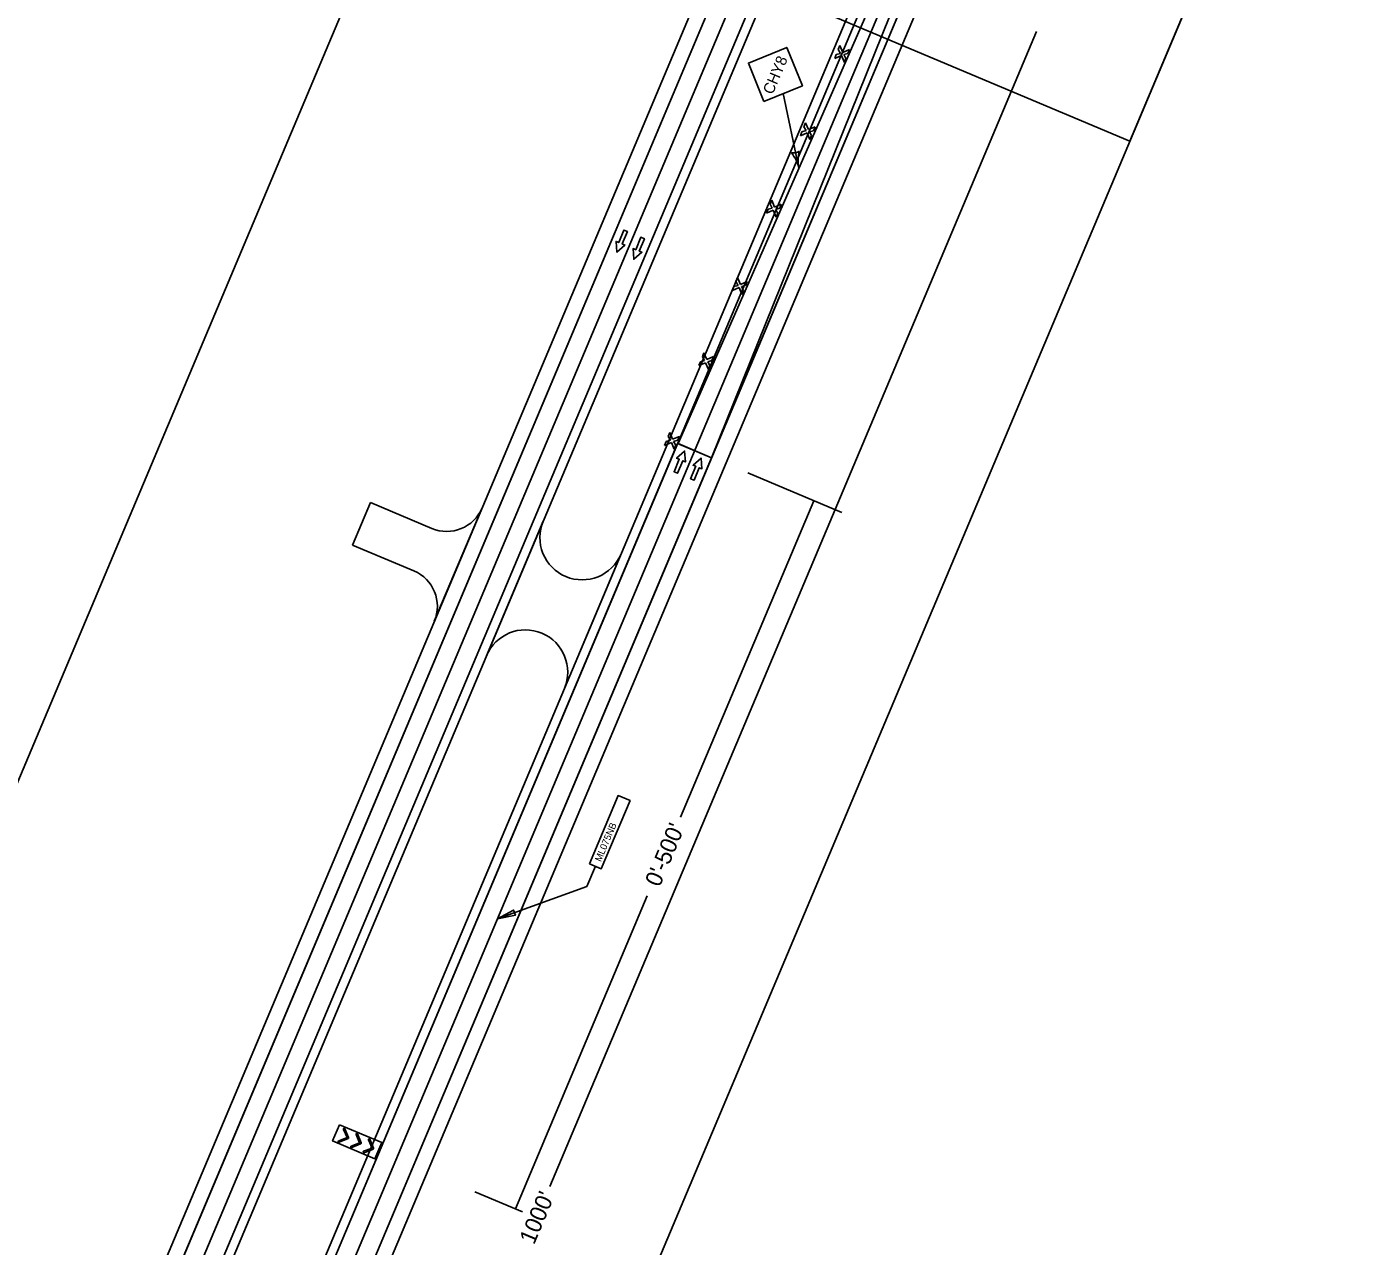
# Model space of a CAD drawing. Extents: x 14104283 to 14128447, y 8633203 to 8671666.
# Drawn here: x 14117804 to 14118675, y 8666247 to 8667040 of the extents above; entities that cross this region are included whole.
import ezdxf

# ---------------------------------------------------------------- set-up
doc = ezdxf.new("R2010")
doc.units = 0
for name, color, linetype in [('Cell', 7, 'Continuous'), ('Default', 7, 'Continuous'), ('dsnNonPlotable', 7, 'Continuous'), ('dsnPaintExistingBrokenLaneLineWhite', 7, 'Continuous'), ('dsnPaintExistingEdgeLineLeftYellow', 7, 'Continuous'), ('dsnPaintExistingEdgeLineRightWhite', 7, 'Continuous'), ('dsnShadingPaved', 7, 'Continuous'), ('dsnStdLabel', 7, 'Continuous'), ('dsnStgShadingPrevPav', 7, 'Continuous'), ('dsnTapePlaceChannelizingLaneYellow', 7, 'Continuous'), ('dsnTapeRemoveChannelizingWhite', 7, 'Continuous'), ('Text', 7, 'Continuous')]:
    doc.layers.add(name, color=color, linetype=linetype)

msp = doc.modelspace()

# ---------------------------------------------------------------- linework, layer by layer
at = {"layer": 'Cell'}
for p, q in [((14118333.3, 8667028.02), (14118332.27, 8667025.47)), ((14118335.17, 8667023.63), (14118333.3, 8667028.02)), ((14118330.96, 8667022.22), (14118329.94, 8667019.67)), ((14118329.94, 8667019.67), (14118334.33, 8667021.54)), ((14118333.7, 8667023), (14118330.96, 8667022.22)), ((14118332.27, 8667025.47), (14118333.7, 8667023)), ((14118334.33, 8667021.54), (14118336.2, 8667017.15)), ((14118339.56, 8667025.5), (14118335.17, 8667023.63)), ((14118335.79, 8667022.16), (14118338.53, 8667022.95)), ((14118337.22, 8667019.7), (14118335.79, 8667022.16)), ((14118336.2, 8667017.15), (14118337.22, 8667019.7)), ((14118338.53, 8667022.95), (14118339.56, 8667025.5)), ((14118310.93, 8666977.77), (14118309.91, 8666975.22)), ((14118309.91, 8666975.22), (14118311.34, 8666972.75)), ((14118312.8, 8666973.37), (14118310.93, 8666977.77)), ((14118317.2, 8666975.24), (14118312.8, 8666973.37)), ((14118316.17, 8666972.69), (14118317.2, 8666975.24)), ((14118308.6, 8666971.97), (14118307.57, 8666969.42)), ((14118307.57, 8666969.42), (14118311.96, 8666971.29)), ((14118311.34, 8666972.75), (14118308.6, 8666971.97)), ((14118311.96, 8666971.29), (14118313.83, 8666966.9)), ((14118313.43, 8666971.91), (14118316.17, 8666972.69)), ((14118314.86, 8666969.45), (14118313.43, 8666971.91)), ((14118313.83, 8666966.9), (14118314.86, 8666969.45)), ((14118289.33, 8666922.35), (14118286.59, 8666921.57)), ((14118288.92, 8666927.37), (14118287.89, 8666924.81)), ((14118287.89, 8666924.81), (14118289.33, 8666922.35)), ((14118290.79, 8666922.97), (14118288.92, 8666927.37)), ((14118295.18, 8666924.84), (14118290.79, 8666922.97)), ((14118291.41, 8666921.51), (14118294.16, 8666922.29)), ((14118294.16, 8666922.29), (14118295.18, 8666924.84)), ((14118286.59, 8666921.57), (14118285.56, 8666919.02)), ((14118285.56, 8666919.02), (14118289.95, 8666920.89)), ((14118289.95, 8666920.89), (14118291.82, 8666916.5)), ((14118292.85, 8666919.05), (14118291.41, 8666921.51)), ((14118291.82, 8666916.5), (14118292.85, 8666919.05)), ((14118264.35, 8666871.26), (14118263.32, 8666868.71)), ((14118263.32, 8666868.71), (14118267.71, 8666870.58)), ((14118267.09, 8666872.04), (14118264.35, 8666871.26)), ((14118266.69, 8666877.06), (14118265.66, 8666874.51)), ((14118265.66, 8666874.51), (14118267.09, 8666872.04)), ((14118268.56, 8666872.67), (14118266.69, 8666877.06)), ((14118267.71, 8666870.58), (14118269.58, 8666866.19)), ((14118272.95, 8666874.54), (14118268.56, 8666872.67)), ((14118269.18, 8666871.2), (14118271.92, 8666871.99)), ((14118270.61, 8666868.74), (14118269.18, 8666871.2)), ((14118271.92, 8666871.99), (14118272.95, 8666874.54)), ((14118269.58, 8666866.19), (14118270.61, 8666868.74)), ((14118244.83, 8666828.19), (14118243.8, 8666825.64)), ((14118246.7, 8666823.8), (14118244.83, 8666828.19)), ((14118242.49, 8666822.39), (14118241.46, 8666819.84)), ((14118241.46, 8666819.84), (14118245.86, 8666821.71)), ((14118245.23, 8666823.18), (14118242.49, 8666822.39)), ((14118243.8, 8666825.64), (14118245.23, 8666823.18)), ((14118245.86, 8666821.71), (14118247.73, 8666817.32)), ((14118251.09, 8666825.67), (14118246.7, 8666823.8)), ((14118247.32, 8666822.33), (14118250.06, 8666823.12)), ((14118248.75, 8666819.87), (14118247.32, 8666822.33)), ((14118247.73, 8666817.32), (14118248.75, 8666819.87)), ((14118250.06, 8666823.12), (14118251.09, 8666825.67)), ((14118222.59, 8666776.29), (14118221.56, 8666773.74)), ((14118224.46, 8666771.9), (14118222.59, 8666776.29)), ((14118220.25, 8666770.49), (14118219.23, 8666767.94)), ((14118219.23, 8666767.94), (14118223.62, 8666769.81)), ((14118223, 8666771.27), (14118220.25, 8666770.49)), ((14118221.56, 8666773.74), (14118223, 8666771.27)), ((14118223.62, 8666769.81), (14118225.49, 8666765.42)), ((14118228.85, 8666773.77), (14118224.46, 8666771.9)), ((14118225.08, 8666770.43), (14118227.82, 8666771.22)), ((14118226.52, 8666767.97), (14118225.08, 8666770.43)), ((14118225.49, 8666765.42), (14118226.52, 8666767.97)), ((14118227.82, 8666771.22), (14118228.85, 8666773.77)), ((14118013.61, 8666317.52), (14118011.26, 8666323.29)), ((14118021.74, 8666314.1), (14118019.39, 8666319.86)), ((14118029.82, 8666310.69), (14118027.47, 8666316.46))]:
    msp.add_line(p, q, dxfattribs=at)
for points in [[(14118192.67, 8666908.01), (14118194.98, 8666907.06), (14118191.66, 8666898.97), (14118193.4, 8666898.26), (14118188.13, 8666893.66), (14118187.61, 8666900.63), (14118189.35, 8666899.92)], [(14118203.74, 8666903.35), (14118206.05, 8666902.4), (14118202.73, 8666894.31), (14118204.46, 8666893.6), (14118199.2, 8666889), (14118198.68, 8666895.97), (14118200.41, 8666895.26)], [(14118227.71, 8666749.82), (14118225.4, 8666750.77), (14118228.72, 8666758.87), (14118226.99, 8666759.58), (14118232.25, 8666764.17), (14118232.77, 8666757.21), (14118231.03, 8666757.92)], [(14118238.48, 8666745.29), (14118236.17, 8666746.23), (14118239.49, 8666754.33), (14118237.76, 8666755.04), (14118243.02, 8666759.64), (14118243.54, 8666752.67), (14118241.8, 8666753.38)], [(14118007.58, 8666325.88), (14118035.23, 8666314.23), (14118030.78, 8666303.66), (14118003.13, 8666315.31)]]:
    msp.add_lwpolyline(points, close=True, dxfattribs=at)
for points in [[(14118189.35, 8666899.92), (14118187.61, 8666900.63), (14118188.13, 8666893.66), (14118193.4, 8666898.26), (14118191.66, 8666898.97), (14118194.98, 8666907.06), (14118192.67, 8666908.01), (14118189.35, 8666899.92)], [(14118200.41, 8666895.26), (14118198.68, 8666895.97), (14118199.2, 8666889), (14118204.46, 8666893.6), (14118202.73, 8666894.31), (14118206.05, 8666902.4), (14118203.74, 8666903.35), (14118200.41, 8666895.26)], [(14118231.03, 8666757.92), (14118232.77, 8666757.21), (14118232.25, 8666764.17), (14118226.99, 8666759.58), (14118228.72, 8666758.87), (14118225.4, 8666750.77), (14118227.71, 8666749.82), (14118231.03, 8666757.92)], [(14118241.8, 8666753.38), (14118243.54, 8666752.67), (14118243.02, 8666759.64), (14118237.76, 8666755.04), (14118239.49, 8666754.33), (14118236.17, 8666746.23), (14118238.48, 8666745.29), (14118241.8, 8666753.38)], [(14118010.3, 8666322.91), (14118010.31, 8666322.88), (14118012.66, 8666317.52), (14118007.18, 8666315.45)], [(14118007.54, 8666314.49), (14118007.56, 8666314.49), (14118013.32, 8666316.84), (14118013.33, 8666316.84)], [(14118018.43, 8666319.48), (14118018.45, 8666319.45), (14118020.79, 8666314.09), (14118015.31, 8666312.03)], [(14118015.67, 8666311.06), (14118015.69, 8666311.07), (14118021.45, 8666313.42), (14118021.46, 8666313.42)], [(14118026.52, 8666316.07), (14118026.53, 8666316.05), (14118028.87, 8666310.69), (14118023.39, 8666308.62)], [(14118023.75, 8666307.66), (14118023.77, 8666307.66), (14118029.54, 8666310.01), (14118029.54, 8666310.01)]]:
    msp.add_lwpolyline(points, dxfattribs=at)
for centre, start, end in [((14118010.78, 8666323.1), 21.87368, 202.05724), ((14118007.35, 8666314.97), 109.79452, 290.9537), ((14118013.13, 8666317.32), 292.54487, 22.99314), ((14118018.91, 8666319.67), 21.87368, 202.05724), ((14118021.26, 8666313.89), 292.54487, 22.99314), ((14118026.99, 8666316.27), 21.87368, 202.05724), ((14118015.49, 8666311.54), 109.79452, 290.9537), ((14118023.57, 8666308.14), 109.79452, 290.9537), ((14118029.35, 8666310.49), 292.54487, 22.99314)]:
    msp.add_arc(centre, 0.515, start, end, dxfattribs=at)
at = {"layer": 'Default'}
for points in [[(14118413.25, 8667444.25), (14110818.39, 8649409.15), (14109142.61, 8645431.44)], [(14109164.73, 8645422.12), (14110840.51, 8649399.84), (14118435.37, 8667434.94)]]:
    msp.add_lwpolyline(points, dxfattribs=at)
at = {"layer": 'dsnNonPlotable'}
for points in [[(14118056.48, 8667161.91), (14118665.06, 8668606.45), (14119130.44, 8668410.38), (14118521.87, 8666965.84)], [(14117486.73, 8665809.52), (14118095.31, 8667254.06), (14118560.69, 8667058), (14117952.12, 8665613.46)]]:
    msp.add_lwpolyline(points, close=True, dxfattribs=at)
at = {"layer": 'dsnPaintExistingBrokenLaneLineWhite'}
for p, q in [((14114932.53, 8658913.38), (14118537.63, 8667474.22)), ((14110829.45, 8649404.5), (14118424.31, 8667439.59))]:
    msp.add_line(p, q, dxfattribs=at)
at = {"layer": 'dsnPaintExistingEdgeLineLeftYellow'}
for p, q in [((14115900.95, 8661243.95), (14118759.37, 8668031.7)), ((14118435.37, 8667434.94), (14115816.14, 8661215.2))]:
    msp.add_line(p, q, dxfattribs=at)
at = {"layer": 'dsnPaintExistingEdgeLineRightWhite'}
for p, q in [((14110924.38, 8649364.51), (14118874.68, 8668243.67)), ((14118413.25, 8667444.25), (14115798.75, 8661235.75))]:
    msp.add_line(p, q, dxfattribs=at)
at = {"layer": 'dsnShadingPaved'}
for p, q in [((14118249.84, 8666759.92), (14118874.67, 8668243.66)), ((14118537.63, 8667474.22), (14118227.96, 8666769.13)), ((14115901.18, 8661244.5), (14118227.72, 8666769.23)), ((14118227.72, 8666769.23), (14118249.84, 8666759.92)), ((14118227.96, 8666769.13), (14118249.84, 8666759.92)), ((14118249.84, 8666759.92), (14115923.29, 8661235.18))]:
    msp.add_line(p, q, dxfattribs=at)
at = {"layer": 'dsnStdLabel'}
for p, q in [((14118461.19, 8667037.24), (14118330.11, 8666726.11)), ((14118296.4, 8666996.79), (14118306.61, 8666948.21)), ((14118334.65, 8666724.2), (14118273.35, 8666750.02)), ((14118316.29, 8666731.94), (14118229.56, 8666526.07)), ((14118330.11, 8666726.11), (14118144.58, 8666285.72)), ((14118207.93, 8666474.74), (14118122.17, 8666271.16)), ((14118126.78, 8666269.22), (14118095.84, 8666282.24))]:
    msp.add_line(p, q, dxfattribs=at)
msp.add_lwpolyline([(14118283.9, 8666991.7), (14118308.9, 8667001.88), (14118298.72, 8667026.88), (14118273.72, 8667016.7)], close=True, dxfattribs=at)
for centre, radius, start, end in [((14118302.65, 8666967.04), 8.86, 264.12916, 299.59761), ((14118284.15, 8666943.49), 22.95, 11.86334, 39.9346), ((14118329.06, 8666952.93), 22.95, 163.79218, 191.86349)]:
    msp.add_arc(centre, radius, start, end, dxfattribs=at)
at = {"layer": 'dsnStgShadingPrevPav'}
for p, q in [((14115895.65, 8661246.83), (14118811.53, 8668171.01)), ((14118848.39, 8668155.49), (14115932.51, 8661231.3)), ((14118653.02, 8668013.62), (14115794.02, 8661224.52)), ((14115816.14, 8661215.2), (14118675.14, 8668004.3)), ((14115816.14, 8661215.2), (14118675.14, 8668004.3)), ((14118680.66, 8668001.98), (14115821.67, 8661212.88)), ((14110809.18, 8649413.03), (14118404.03, 8667448.13)), ((14118413.25, 8667444.25), (14110818.39, 8649409.15)), ((14118027.88, 8666730.65), (14118016.23, 8666703)), ((14118067.7, 8666713.88), (14118027.88, 8666730.65)), ((14118069.39, 8666653.49), (14118100.44, 8666727.21)), ((14118140.22, 8666718.6), (14118103.35, 8666631.05)), ((14118016.23, 8666703), (14118056.06, 8666686.23)), ((14118154.04, 8666609.7), (14118190.91, 8666697.26))]:
    msp.add_line(p, q, dxfattribs=at)
for centre, radius, start, end in [((14118077.4, 8666736.92), 25, 247.1633, 337.1633), ((14118165.56, 8666707.93), 27.5, 157.1633, 247.1633), ((14118165.56, 8666707.93), 27.5, 247.1633, 337.1633), ((14118046.35, 8666663.19), 25, 337.1633, 67.1633), ((14118128.69, 8666620.38), 27.5, 67.1633, 157.1633), ((14118128.69, 8666620.38), 27.5, 337.1633, 67.1633)]:
    msp.add_arc(centre, radius, start, end, dxfattribs=at)
at = {"layer": 'dsnTapePlaceChannelizingLaneYellow'}
msp.add_line((14118227.96, 8666769.13), (14118537.63, 8667474.22), dxfattribs=at)
at = {"layer": 'dsnTapeRemoveChannelizingWhite'}
msp.add_line((14118249.84, 8666759.92), (14118537.63, 8667474.22), dxfattribs=at)
at = {"layer": 'Text'}
for points in [[(14118170.31, 8666495.71), (14118188.98, 8666540.05), (14118196.72, 8666536.78), (14118178.05, 8666492.45)], [(14118170.31, 8666495.71), (14118188.98, 8666540.05), (14118196.72, 8666536.78), (14118178.05, 8666492.45)], [(14118110.47, 8666459.86), (14118120.97, 8666465.56), (14118122.17, 8666462.23)]]:
    msp.add_lwpolyline(points, close=True, dxfattribs=at)
msp.add_lwpolyline([(14118174.18, 8666494.08), (14118168.54, 8666480.93), (14118110.47, 8666459.86)], dxfattribs=at)

# ---------------------------------------------------------------- texts
at = {"layer": 'dsnStdLabel'}
for s, height, p in [('CHY8', 7.2, (14118289.5, 8666995.73)), ("0'-500'", 10.8, (14118216.02, 8666480.03)), ("1000'", 10.8, (14118134.28, 8666247.35))]:
    msp.add_text(s, height=height, rotation=67.1547, dxfattribs=at).set_placement(p)
at = {"layer": 'Text'}
msp.add_text('ML075NB', height=4.484, rotation=67.1547, dxfattribs=at).set_placement((14118177.77, 8666496.68))

doc.saveas('drawing.dxf')
